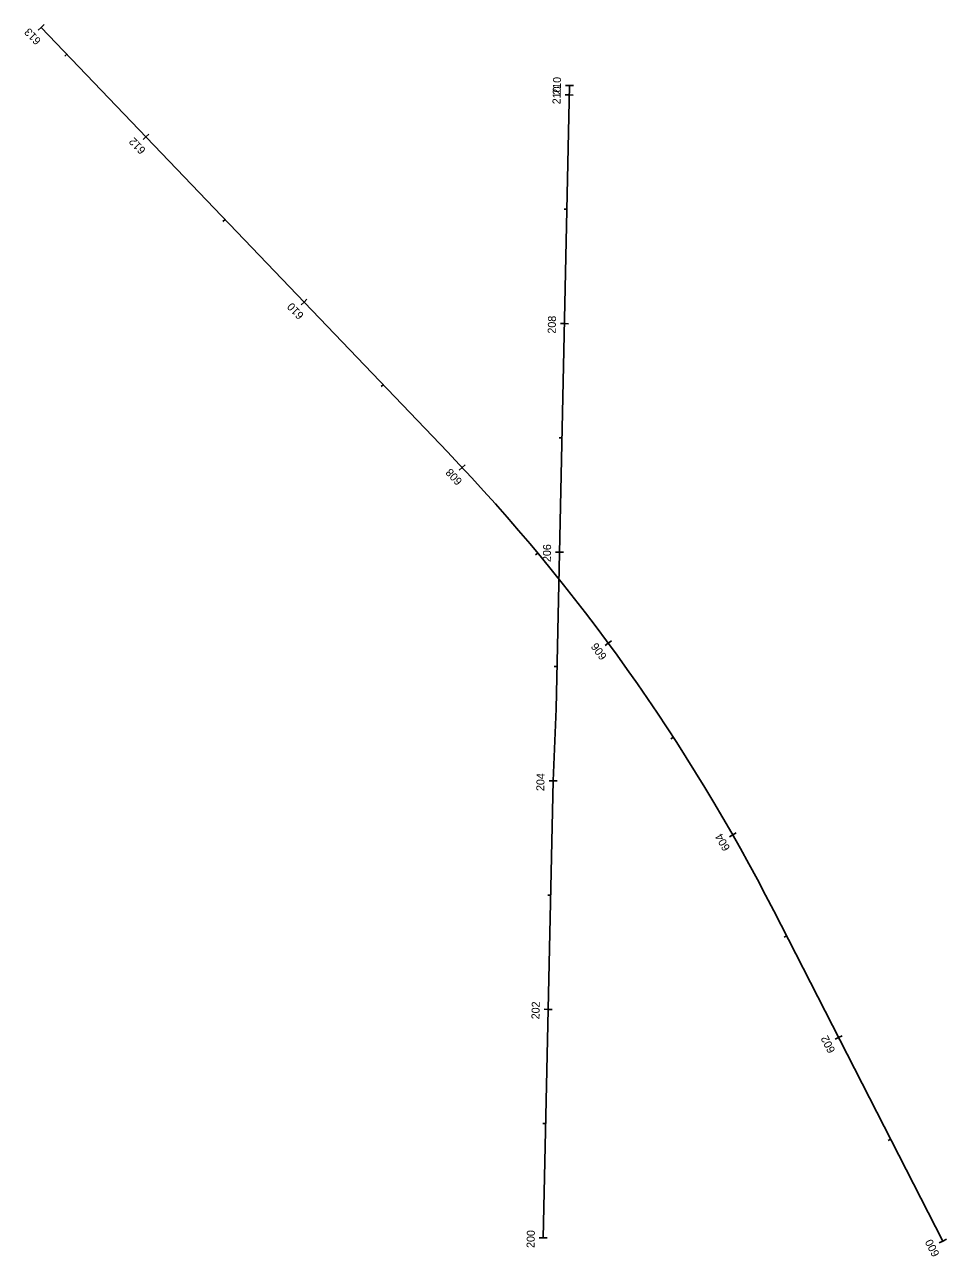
# Model space of a CAD drawing. Extents: x 596008 to 607538, y 326212 to 405053.
# Drawn here: x 596008 to 596813, y 342744 to 343822 of the extents above; entities that cross this region are included whole.
import ezdxf

# ---------------------------------------------------------------- set-up
doc = ezdxf.new("R2010")
doc.units = 0
for name, color, linetype in [('P_ALI', 7, 'Continuous'), ('P_ALI_200', 7, 'Continuous'), ('P_ALI_200_Sta', 7, 'Continuous'), ('P_ALI_200_Tic', 7, 'Continuous')]:
    doc.layers.add(name, color=color, linetype=linetype)

msp = doc.modelspace()

# ---------------------------------------------------------------- linework, layer by layer
at = {"layer": 'P_ALI'}
for points in [[(596472.2, 343223.3), (596483.8, 343768.5)], [(596469.4, 343160.3), (596472.2, 343223.3)], [(596460.9, 342760.4), (596469.4, 343160.3)]]:
    msp.add_lwpolyline(points, dxfattribs=at)
at = {"layer": 'P_ALI_200'}
for points in [[(596377.2, 343448), (596022, 343819.3)], [(596810.1, 342757.7), (596662.4, 343046.6)]]:
    msp.add_lwpolyline(points, dxfattribs=at)
msp.add_arc((595148.5, 342273), 1700, 27.0674, 43.7214, dxfattribs=at)
at = {"layer": 'P_ALI_200_Sta'}
for points in [[(596024.6, 343821.8), (596022, 343819.3)], [(596022, 343819.3), (596019.5, 343816.9)], [(596022, 343819.3), (596022, 343819.3)], [(596483.8, 343768.5), (596480.3, 343768.6)], [(596483.8, 343768.5), (596483.8, 343768.5)], [(596487.3, 343768.4), (596483.8, 343768.5)], [(596483.6, 343760.2), (596480.1, 343760.2)], [(596483.6, 343760.2), (596483.6, 343760.2)], [(596487.1, 343760.1), (596483.6, 343760.2)], [(596116.1, 343726), (596113.6, 343723.6)], [(596113.6, 343723.6), (596111, 343721.2)], [(596113.6, 343723.6), (596113.6, 343723.6)], [(596251.8, 343579.1), (596249.3, 343576.6)], [(596254.3, 343581.5), (596251.8, 343579.1)], [(596251.8, 343579.1), (596251.8, 343579.1)], [(596479.4, 343560.2), (596475.9, 343560.3)], [(596479.4, 343560.2), (596479.4, 343560.2)], [(596482.9, 343560.1), (596479.4, 343560.2)], [(596390, 343434.5), (596387.4, 343432.1)], [(596392.5, 343436.8), (596390, 343434.5)], [(596390, 343434.5), (596390, 343434.5)], [(596475.1, 343360.3), (596471.6, 343360.3)], [(596475.1, 343360.3), (596475.1, 343360.3)], [(596478.6, 343360.2), (596475.1, 343360.3)], [(596520.5, 343282.8), (596517.7, 343280.7)], [(596517.7, 343280.7), (596514.9, 343278.6)], [(596517.7, 343280.7), (596517.7, 343280.7)], [(596469.4, 343160.3), (596465.9, 343160.4)], [(596469.4, 343160.3), (596469.4, 343160.3)], [(596472.9, 343160.3), (596469.4, 343160.3)], [(596626.5, 343113), (596623.5, 343111.3)], [(596629.6, 343114.8), (596626.5, 343113)], [(596626.5, 343113), (596626.5, 343113)], [(596465.2, 342960.4), (596461.7, 342960.5)], [(596465.2, 342960.4), (596465.2, 342960.4)], [(596468.7, 342960.3), (596465.2, 342960.4)], [(596722.1, 342937.3), (596719, 342935.7)], [(596719, 342935.7), (596715.9, 342934.2)], [(596719, 342935.7), (596719, 342935.7)], [(596460.9, 342760.4), (596457.4, 342760.5)], [(596460.9, 342760.4), (596460.9, 342760.4)], [(596464.4, 342760.4), (596460.9, 342760.4)], [(596810.1, 342757.7), (596806.9, 342756.1)], [(596813.2, 342759.3), (596810.1, 342757.7)], [(596810.1, 342757.7), (596810.1, 342757.7)]]:
    msp.add_lwpolyline(points, dxfattribs=at)
at = {"layer": 'P_ALI_200_Tic'}
for points in [[(596044.5, 343795.9), (596042.6, 343794.2)], [(596481.5, 343660.2), (596479, 343660.2)], [(596182.7, 343651.3), (596180.9, 343649.6)], [(596320.9, 343506.8), (596319.1, 343505.1)], [(596477.3, 343460.2), (596474.8, 343460.3)], [(596456.1, 343359.5), (596454.2, 343357.9)], [(596473, 343260.3), (596470.5, 343260.3)], [(596574.6, 343198.5), (596572.5, 343197.1)], [(596467.3, 343060.4), (596464.8, 343060.4)], [(596673.5, 343024.8), (596671.3, 343023.6)], [(596463, 342860.4), (596460.5, 342860.5)], [(596764.5, 342846.7), (596762.3, 342845.6)]]:
    msp.add_lwpolyline(points, dxfattribs=at)

# ---------------------------------------------------------------- texts
at = {"layer": 'P_ALI_200_Sta'}
for s, rotation, p in [('613', 133.7214, (596022.4, 343808.1)), ('210', 88.7864, (596475.9, 343752)), ('210', 88.7864, (596476.1, 343760.3)), ('612', 133.7214, (596113.9, 343712.4)), ('610', 133.7214, (596252.1, 343567.9)), ('208', 88.7864, (596471.7, 343551.4)), ('608', 133.0935, (596390.6, 343422.8)), ('206', 88.7864, (596467.4, 343351.6)), ('606', 126.3528, (596516.9, 343269.2)), ('204', 88.7864, (596461.7, 343151.3)), ('604', 119.6121, (596624.5, 343101.4)), ('202', 88.7864, (596457.5, 342951.6)), ('602', 117.0773, (596716.4, 342924.3)), ('200', 88.7864, (596453.2, 342751.6)), ('600', 117.0773, (596807.5, 342746.2))]:
    msp.add_text(s, height=7, rotation=rotation, dxfattribs=at).set_placement(p)

doc.saveas('drawing.dxf')
